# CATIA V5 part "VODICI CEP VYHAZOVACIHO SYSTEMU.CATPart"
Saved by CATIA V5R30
Part number: VODICI CEP VYHAZOVACIHO SYSTEMU
Bounding box of the stored display mesh (mm): x 0 to 140, y -11.99 to 11.99, z -12 to 12
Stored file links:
  C:\Users\ondra\Desktop\PŘÍLOHA P III\CATIA\VODICI CEP VYHAZOVACIHO SYSTEMU.CATPart
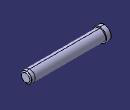
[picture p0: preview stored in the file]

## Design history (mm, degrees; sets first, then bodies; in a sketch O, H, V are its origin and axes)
Set1
  DatumSurface1 to DatumSurface17 "Z01/20x1"
  Join1: Elements (DatumSurface1; DatumSurface2; DatumSurface3; DatumSurface4; DatumSurface5; DatumSurface6; DatumSurface7; DatumSurface8; DatumSurface9; DatumSurface10; DatumSurface11; DatumSurface12; DatumSurface13; DatumSurface14; DatumSurface15; DatumSurface16; DatumSurface17)
Body1 (main body)
  CloseSurface1: CloseElement Join1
